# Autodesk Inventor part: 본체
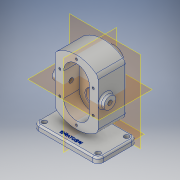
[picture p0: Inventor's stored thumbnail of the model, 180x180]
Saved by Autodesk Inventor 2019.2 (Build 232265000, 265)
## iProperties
Created: 2019-03
Part Number: 본체
Material: 알루미늄 6061
Document SubType Name: Modeling
Designer: User
Density: 2.7 g/cm^3
Appearance: 알루미늄 - 평지
Mass: 1185.36 g
Surface Area: 720.534 cm^2
Volume: 439.024 cm^3
Author: User
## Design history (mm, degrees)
sketch "스케치1"
  geometry: L1 (0, 84)-(0, -84) reference; L2 (-56, 0)-(56, 0) reference; L3 (-40, 44.721)-(-40, -44.721); L4 (40, -44.721)-(40, 44.721); A1 r 60 centre (0, 0) between (-40, -44.721) and (40, -44.721); A2 r 60 centre (0, 0) between (40, 44.721) and (-40, 44.721); 1 further point
  constraints: 4 end point, 4 point on circle, 2 centre point, 2 vertical, 1 coincident
  dimensions: "d1" = 80 distance between parallel lines of L4 L3; "d2" = 40 distance between parallel lines of L4 L1; "d3" = 60 radius of A2; "d4" = 60 radius of A1
extrude "돌출1" new body sketch "스케치1" distance "d5" = 53; taper "d6" = 0 deg
sketch "스케치2"
  geometry: L1 (0, 84)-(0, -84) reference; C1 r 19 at (0, 22); 1 further point
  constraints: 1 centre point, 1 point on line
  dimensions: "d7" = 38 diameter of C1; "d8" = 22 distance of point (0, 0) C1.centre
extrude "돌출2" join sketch "스케치2" distance "d9" = 70; taper "d10" = 0 deg
sketch "스케치3"
  geometry: L1 (44.721, 53)-(-44.721, 53) reference; L2 (0, 67)-(0, -31) reference; C1 r 11 at (0, 39); 1 further point
  constraints: 1 centre point, 1 point on line
  dimensions: "d11" = 22 diameter of C1; "d12" = 14 distance from line of L1 C1.centre
extrude "돌출3" join sketch "스케치3" stored distance "d13" = 96; taper "d14" = 0 deg
node "작업 평면1"
sketch "스케치4"
  geometry: L1 (60, 0)-(-60, 0); L2 (-60, 0)-(-60, 73); L3 (-60, 73)-(60, 73); L4 (60, 73)-(60, 0); L5 (0, -35)-(0, 91) reference; L6 (-84, 0)-(84, 0) reference; 1 further point
  constraints: 8 end point, 2 parallel, 1 collinear, 1 horizontal, 1 perpendicular
  dimensions: "d16" = 73 distance of L3.end L1.start; "d17" = 120 distance of L2.end L3.end; "d18" = 60 distance between parallel lines of L5 L4
extrude "돌출4" join sketch "스케치4" distance "d19" = 10; taper "d20" = 0 deg
sketch "스케치5"
  geometry: L1 (-45.169, 43)-(-68, 43); L2 (-68, 43)-(-68, 0); L3 (-68, 0)-(-45.169, 0); L4 (-45.169, 0)-(-45.169, 43); L5 (-68, 0)-(-68, 73) reference; L6 (-78, 0)-(-68, 0) reference; 1 further point
  constraints: 8 end point, 2 collinear, 2 parallel, 1 horizontal, 1 perpendicular
  dimensions: "d21" = 43 distance of L1.end L2.end; "d22" = 22.83133 distance of L1.start L1.end
extrude "돌출5" join sketch "스케치5" stored distance "d23" = 12; taper "d24" = 0 deg
sketch "스케치6"
  geometry: L1 (0, -22)-(0, 22); L2 (24, -22)-(24, 22); L3 (-24, 22)-(-24, -22); L4 (-84, 0)-(84, 0) reference; L5 (0, -105.6)-(0, 87.6) reference; A1 r 24 centre (0, -22) between (-24, -22) and (24, -22); A2 r 24 centre (0, 22) between (24, 22) and (-24, 22); 2 further points
  constraints: 8 end point, 4 point on circle, 4 tangent, 2 centre point, 1 collinear, 1 midpoint, 1 parallel, 1 vertical, 1 other
  dimensions: "d25" = 24 radius of A2; "d26" = 44 distance of L2.start L2.end
extrude "돌출6" cut sketch "스케치6" distance "d27" = 29; taper "d28" = 0 deg
sketch "스케치7"
  geometry: A1 r 24 centre (0, 22) between (24, 22) and (-24, 22) reference; 2 further points
  constraints: 1 coincident
hole "구멍1" sketch "스케치7" at (0, 22) diameter "d29" = 17; stored, may be unused: countersink angle "d33" = 90 deg, drill point angle "d35" = 118 deg; dims "d30" = 9, "d31" = 25, "d32" = 17, "d34" = 50
sketch "스케치8"
  geometry: A1 r 24 centre (0, -22) between (-24, -22) and (24, -22) reference; 2 further points
  constraints: 1 coincident
hole "구멍2" sketch "스케치8" at (0, -22) diameter "d36" = 25; stored, may be unused: countersink angle "d40" = 90 deg, drill point angle "d42" = 0 deg; dims "d37" = 9, "d38" = 25, "d39" = 17, "d41" = 15
sketch "스케치9"
  geometry: C1 r 19 at (0, 0) reference; 2 further points
  constraints: 1 coincident
hole "구멍3" sketch "스케치9" at (0, 0) diameter "d43" = 28; stored, may be unused: countersink angle "d47" = 90 deg, drill point angle "d49" = 0 deg; dims "d44" = 9, "d45" = 25, "d46" = 17, "d48" = 7.3
sketch "스케치10"
  geometry: C1 r 11 at (0, 0) reference; 2 further points
  constraints: 1 coincident
hole "구멍4" sketch "스케치10" at (0, 0) diameter "d50" = 8.376; stored, may be unused: countersink angle "d54" = 90 deg, drill point angle "d56" = 0 deg; dims "d51" = 50, "d52" = 25, "d53" = 17, "d55" = 50
sketch "스케치11"
  geometry: C1 r 11 at (0, 0) reference; 2 further points
  constraints: 1 coincident
hole "구멍5" sketch "스케치11" at (0, 0) diameter "d57" = 8.376; stored, may be unused: countersink angle "d61" = 90 deg, drill point angle "d63" = 0 deg; dims "d58" = 50, "d59" = 25, "d60" = 17, "d62" = 50
sketch "스케치12"
  geometry: L1 (-24, -22)-(-24, 22) reference; L2 (24, 22)-(24, -22) reference; L3 (-31, 22)-(-31, -22); L4 (31, -22)-(31, 22); A1 r 24 centre (0, 22) between (24, 22) and (-24, 22) reference; A2 r 24 centre (0, -22) between (-24, -22) and (24, -22) reference; A3 r 31 centre (0, -22) between (-31, -22) and (31, -22); A4 r 31 centre (0, 22) between (31, 22) and (-31, 22); 1 further point
  constraints: 4 end point, 4 point on circle, 2 centre point, 3 other
  dimensions: "d64" = 7 radial gap between concentric circles of A1 A4
hole "구멍6" sketch "스케치12" at (-31, -22), (-31, 22), (31, 22), (31, -22) diameter "d65" = 4.134; stored, may be unused: countersink angle "d69" = 90 deg, drill point angle "d71" = 118 deg; dims "d66" = 10, "d67" = 25, "d68" = 17, "d70" = 12
sketch "스케치13"
  geometry: L1 (0, 0)-(0, 53)
  constraints: 2 end point, 1 vertical
  dimensions: "d72" = 53 distance of L1.start L1.end
hole "구멍7" sketch "스케치13" at (0, 53) diameter "d73" = 4.134; stored, may be unused: countersink angle "d77" = 90 deg, drill point angle "d79" = 118 deg; dims "d74" = 10, "d75" = 25, "d76" = 17, "d78" = 12
chamfer "모따기1" distance "d80" = 1; stored, may be unused: second distance "d81" = 2, angle "d82" = 45 deg
fillet "모깎기1" dims "d83" = 10
sketch "스케치14"
  geometry: A1 r 10 centre (-50, -63) between (-60, -63) and (-50, -73) reference; A2 r 10 centre (-50, -10) between (-50, 0) and (-60, -10) reference; A3 r 10 centre (50, -63) between (50, -73) and (60, -63) reference; A4 r 10 centre (50, -10) between (60, -10) and (50, 0) reference; 5 further points
  constraints: 4 coincident
hole "구멍8" sketch "스케치14" at (-50, -63), (-50, -10), (50, -63), (50, -10) diameter "d84" = 9; stored, may be unused: countersink angle "d88" = 90 deg, drill point angle "d90" = 118 deg; dims "d85" = 10, "d86" = 25, "d87" = 17, "d89" = 12
fillet "모깎기3" dims "d92" = 10
fillet "모깎기4" dims "d93" = 3
fillet "모깎기5" dims "d94" = 3
fillet "모깎기6" dims "d95" = 3
fillet "모깎기7" dims "d96" = 3
fillet "모깎기8" dims "d97" = 0.5
chamfer "모따기2" distance "d98" = 0.7; stored, may be unused: second distance "d99" = 2, angle "d100" = 30 deg
sketch "스케치15"
  geometry: L1 (-60, -10)-(-60, -63) reference; L2 (-50, -73)-(50, -73) reference; 2 further points
  constraints: 1 other
  dimensions: "d101" = 60 distance from line of L1 point (0, -63); "d102" = 10 distance from line of L2 point (0, -63)
feature "엠보싱1" sketch "스케치15" dims "d103" = 0.5, "d104" = 0
node "솔리드1"
mirror "미러1"
other parameters: "d15" = -78
